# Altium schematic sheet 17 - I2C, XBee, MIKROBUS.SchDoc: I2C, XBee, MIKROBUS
size A3; PageSetup: Record=PageOptions¦CenterHorizontal=True¦CenterVertical=True¦PrintScale=0.70¦XCorrection=1.00¦YCorrection=1.00¦PrintKind=0¦BorderSize=5000000¦LeftOffset=0¦BottomOffset=0¦Orientation=2¦PaperLength=4200¦PaperWidth=2970¦Scale=100¦PaperSource=7¦PrintQuality=600¦MediaType=1¦DitherType=10¦PaperKind=A4¦PrintScaleMode=1; Author: Juan Anzola; SheetNumber: 17; SheetTotal: 20
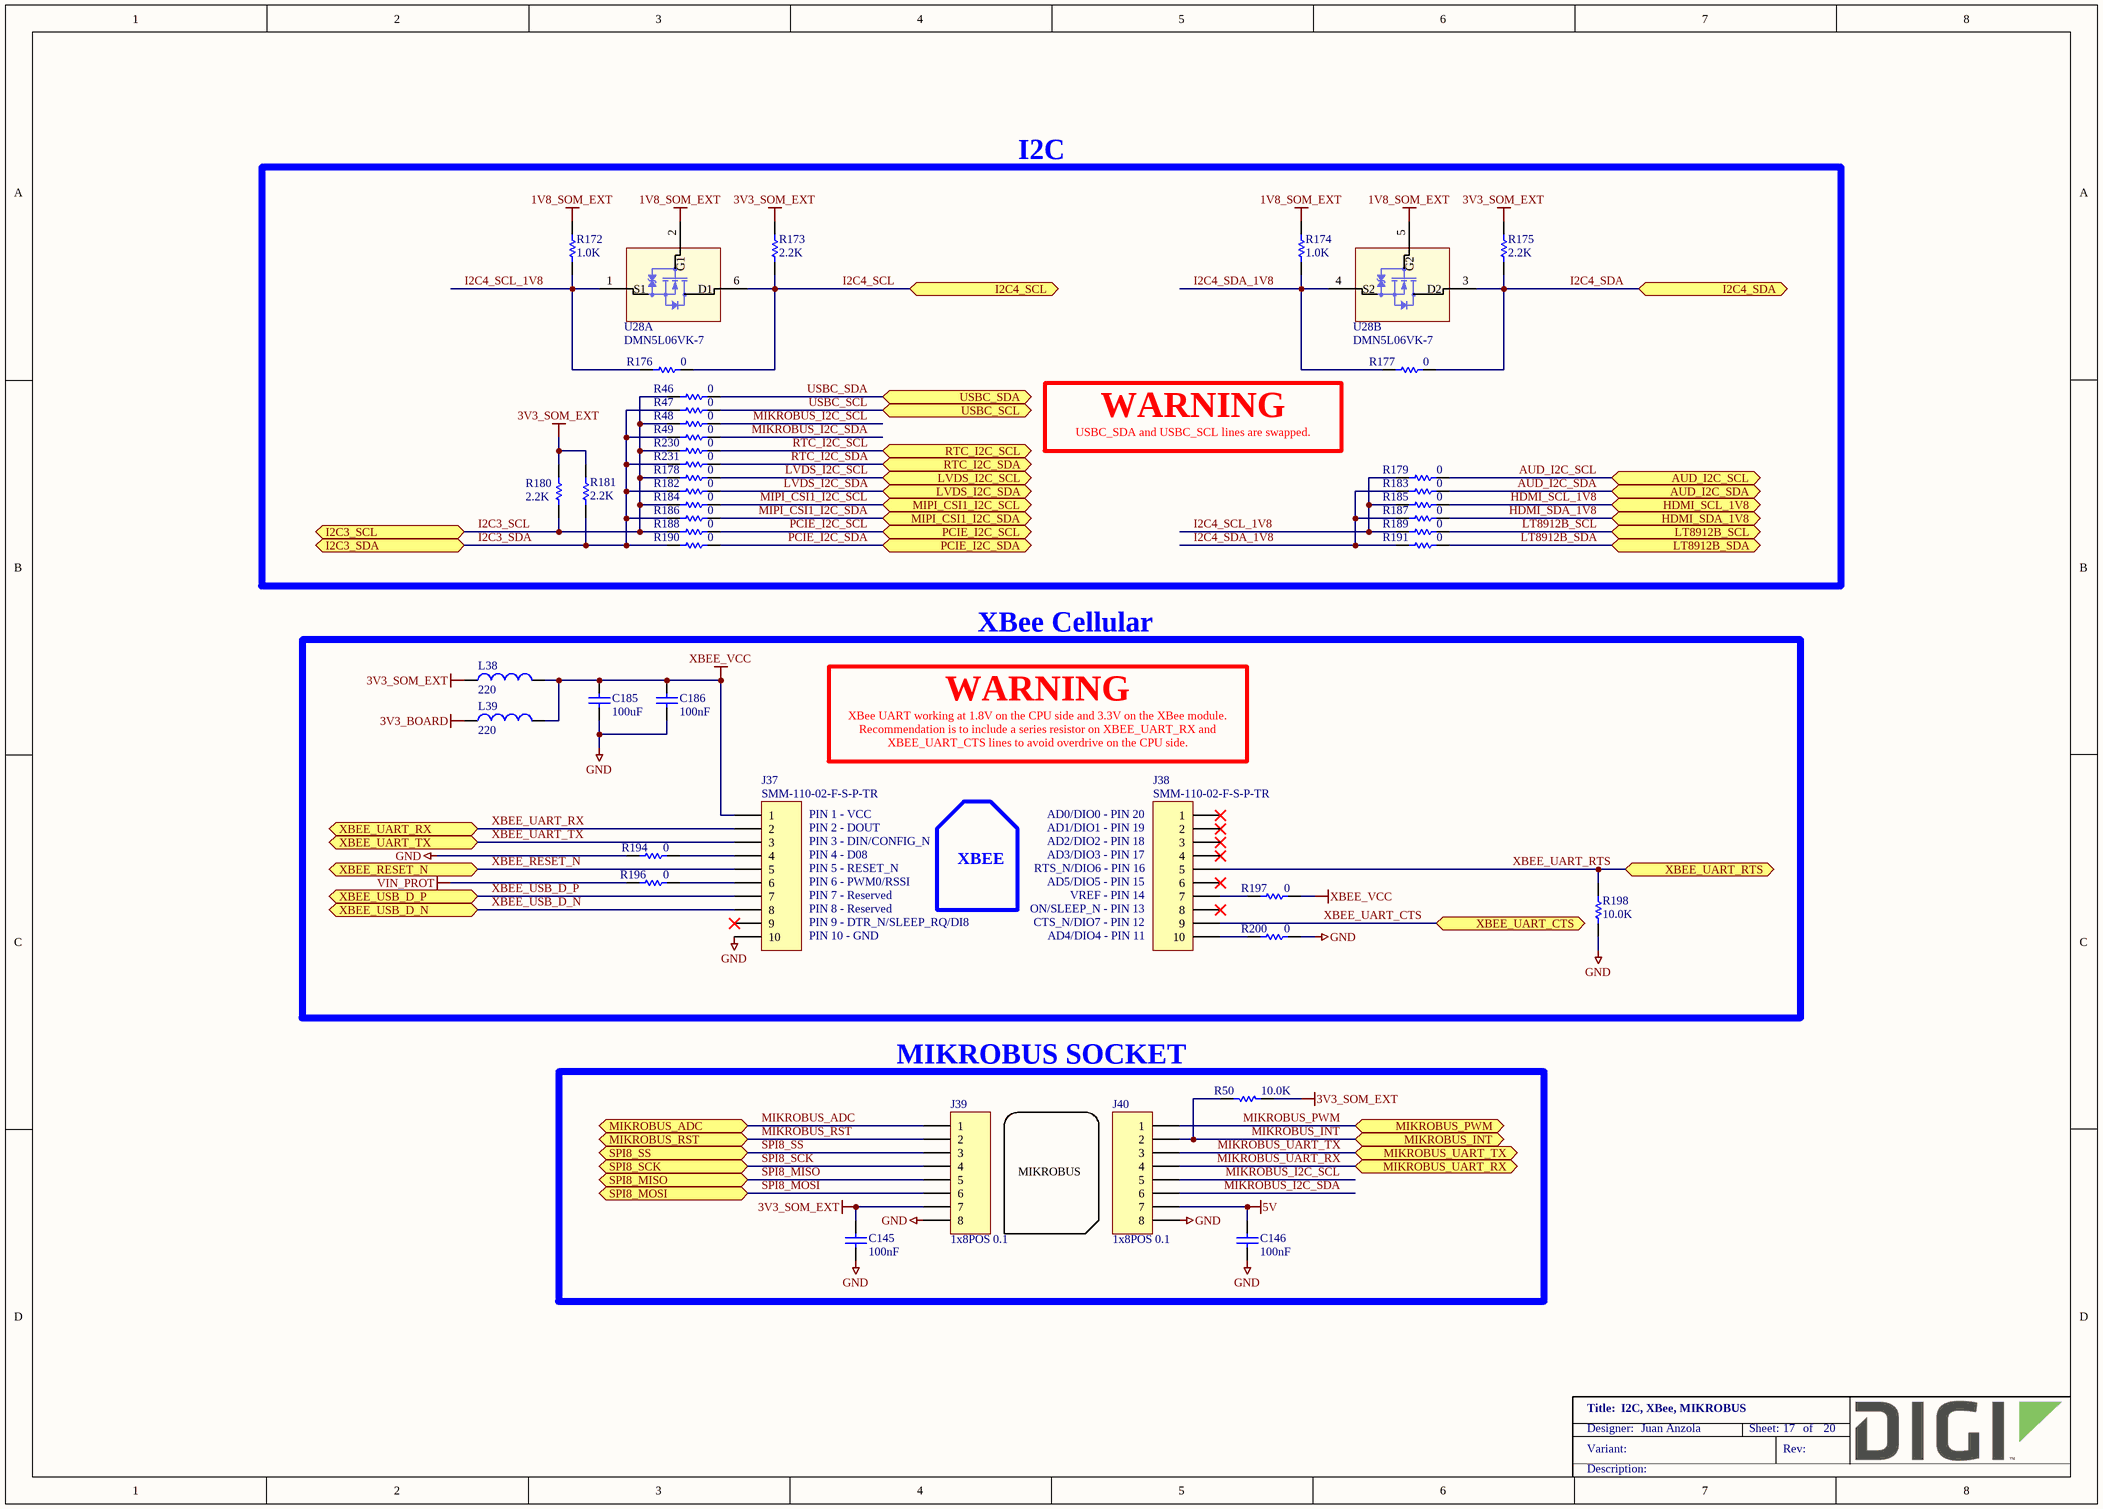
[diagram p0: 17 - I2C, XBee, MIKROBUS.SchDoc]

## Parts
C145  100nF  [CAPC1005X55N]
C146  100nF  [CAPC1005X55N]
C185  100uF  [CAPC3216X190N]
C186  100nF  [CAPC1005X55N]
J37  SMM-110-02-F-S-P-TR  [Samtec_SMM-110-02-F-S]
J38  SMM-110-02-F-S-P-TR  [Samtec_SMM-110-02-F-S]
J39  1x8POS 0.1  [J8_THT_0.1_FEMALE]
J40  1x8POS 0.1  [J8_THT_0.1_FEMALE]
L38  220  [INDC2013X110N]
L39  220  [INDC2013X110N]
R46  0  [RESC1005X40N]
R47  0  [RESC1005X40N]
R48  0  [RESC1005X40N]
R49  0  [RESC1005X40N]
R50  10.0K  [RESC1005X40N]
R172  1.0K  [RESC1005X40N]
R173  2.2K  [RESC1005X40N]
R174  1.0K  [RESC1005X40N]
R175  2.2K  [RESC1005X40N]
R176  0  [RESC1005X40N]
R177  0  [RESC1005X40N]
R178  0  [RESC1005X40N]
R179  0  [RESC1005X40N]
R180  2.2K  [RESC1005X40N]
R181  2.2K  [RESC1005X40N]
R182  0  [RESC1005X40N]
R183  0  [RESC1005X40N]
R184  0  [RESC1005X40N]
R185  0  [RESC1005X40N]
R186  0  [RESC1005X40N]
R187  0  [RESC1005X40N]
R188  0  [RESC1005X40N]
R189  0  [RESC1005X40N]
R190  0  [RESC1005X40N]
R191  0  [RESC1005X40N]
R194  0  [RESC1005X40N]
R196  0  [RESC1005X40N]
R197  0  [RESC1005X40N]
R198  10.0K  [RESC1005X40N]
R200  0  [RESC1005X40N]
R230  0  [RESC1005X40N]
R231  0  [RESC1005X40N]
U28  DMN5L06VK-7  [SOTFL50P160X60-6N]  (parts A,B of 2)

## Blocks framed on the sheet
I2C: R46-R49 R172-R191 R230 R231 U28
XBee Cellular: C185 C186 J37 J38 L38 L39 R194 R196-R198 R200
MIKROBUS SOCKET: C145 C146 J39 J40 R50

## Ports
AUD_I2C_SCL (bidir), AUD_I2C_SDA (bidir), HDMI_SCL_1V8 (bidir), HDMI_SDA_1V8 (bidir), I2C3_SCL (bidir), I2C3_SDA (bidir), I2C4_SCL (bidir), I2C4_SDA (bidir), LT8912B_SCL (bidir), LT8912B_SDA (bidir), LVDS_I2C_SCL (bidir), LVDS_I2C_SDA (bidir), MIKROBUS_ADC (bidir), MIKROBUS_INT (bidir), MIKROBUS_PWM (bidir), MIKROBUS_RST (bidir), MIKROBUS_UART_RX (bidir), MIKROBUS_UART_TX (bidir), MIPI_CSI1_I2C_SCL (bidir), MIPI_CSI1_I2C_SDA (bidir), PCIE_I2C_SCL (bidir), PCIE_I2C_SDA (bidir), RTC_I2C_SCL (bidir), RTC_I2C_SDA (bidir), SPI8_MISO (bidir), SPI8_MOSI (bidir), SPI8_SCK (bidir), SPI8_SS (bidir), USBC_SCL (bidir), USBC_SDA (bidir), XBEE_RESET_N (bidir), XBEE_UART_CTS (bidir), XBEE_UART_RTS (bidir), XBEE_UART_RX (bidir), XBEE_UART_TX (bidir), XBEE_USB_D_N (bidir), XBEE_USB_D_P (bidir)

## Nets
1V8_SOM_EXT: R172.2 R174.2 U28.2(G1) U28.5(G2)
3V3_BOARD: L39.1
3V3_SOM_EXT: C145.2 J39.7 L38.1 R50.2 R173.2 R175.2 R180.2 R181.2
5V: C146.1 J40.7
GND: C145.1 C146.2 C185.1 C186.1 J37.10 J39.8 J40.8 R194.1 R198.1 R200.2
VIN_PROT: R196.1
XBEE_VCC: C185.2 C186.2 J37.1 L38.2 L39.2 R197.2
AUD_I2C_SCL: R179.2 ; port AUD_I2C_SCL
AUD_I2C_SDA: R183.2 ; port AUD_I2C_SDA
HDMI_SCL_1V8: R185.2 ; port HDMI_SCL_1V8
HDMI_SDA_1V8: R187.2 ; port HDMI_SDA_1V8
I2C3_SCL: R46.1 R48.1 R178.1 R180.1 R184.1 R188.1 R230.1 ; port I2C3_SCL
I2C3_SDA: R47.1 R49.1 R181.1 R182.1 R186.1 R190.1 R231.1 ; port I2C3_SDA
I2C4_SCL: R173.1 R176.2 U28.6(D1) ; port I2C4_SCL
I2C4_SCL_1V8: R172.1 R176.1 R179.1 R185.1 R189.1 U28.1(S1)
I2C4_SDA: R175.1 R177.2 U28.3(D2) ; port I2C4_SDA
I2C4_SDA_1V8: R174.1 R177.1 R183.1 R187.1 R191.1 U28.4(S2)
LT8912B_SCL: R189.2 ; port LT8912B_SCL
LT8912B_SDA: R191.2 ; port LT8912B_SDA
LVDS_I2C_SCL: R178.2 ; port LVDS_I2C_SCL
LVDS_I2C_SDA: R182.2 ; port LVDS_I2C_SDA
MIKROBUS_ADC: J39.1 ; port MIKROBUS_ADC
MIKROBUS_I2C_SCL: J40.5 R48.2
MIKROBUS_I2C_SDA: J40.6 R49.2
MIKROBUS_INT: J40.2 R50.1 ; port MIKROBUS_INT
MIKROBUS_PWM: J40.1 ; port MIKROBUS_PWM
MIKROBUS_RST: J39.2 ; port MIKROBUS_RST
MIKROBUS_UART_RX: J40.4 ; port MIKROBUS_UART_RX
MIKROBUS_UART_TX: J40.3 ; port MIKROBUS_UART_TX
MIPI_CSI1_I2C_SCL: R184.2 ; port MIPI_CSI1_I2C_SCL
MIPI_CSI1_I2C_SDA: R186.2 ; port MIPI_CSI1_I2C_SDA
PCIE_I2C_SCL: R188.2 ; port PCIE_I2C_SCL
PCIE_I2C_SDA: R190.2 ; port PCIE_I2C_SDA
RTC_I2C_SCL: R230.2 ; port RTC_I2C_SCL
RTC_I2C_SDA: R231.2 ; port RTC_I2C_SDA
SPI8_MISO: J39.5 ; port SPI8_MISO
SPI8_MOSI: J39.6 ; port SPI8_MOSI
SPI8_SCK: J39.4 ; port SPI8_SCK
SPI8_SS: J39.3 ; port SPI8_SS
USBC_SCL: R47.2 ; port USBC_SCL
USBC_SDA: R46.2 ; port USBC_SDA
XBEE_RESET_N: J37.5 ; port XBEE_RESET_N
XBEE_UART_CTS: J38.9 ; port XBEE_UART_CTS
XBEE_UART_RTS: J38.5 R198.2 ; port XBEE_UART_RTS
XBEE_UART_RX: J37.2 ; port XBEE_UART_RX
XBEE_UART_TX: J37.3 ; port XBEE_UART_TX
XBEE_USB_D_N: J37.8 ; port XBEE_USB_D_N
XBEE_USB_D_P: J37.7 ; port XBEE_USB_D_P
NetJ37_4: J37.4 R194.2
NetJ37_6: J37.6 R196.2
NetJ38_7: J38.7 R197.1
NetJ38_10: J38.10 R200.1

Not connected (* = marked no-connect by the designer): J37 9*; J38 1* 2* 3* 4* 6* 8*

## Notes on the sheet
- WARNING
- USBC_SDA and USBC_SCL lines are swapped.
- XBee UART working at 1.8V on the CPU side and 3.3V on the XBee module. Recommendation is to include a series resistor on XBEE_UART_RX and XBEE_UART_CTS lines to avoid overdrive on the CPU side.
- (near J37) PIN 1 - VCC
- (near J37) PIN 2 - DOUT
- (near J37) PIN 3 - DIN/CONFIG_N
- (near J37) PIN 4 - D08
- (near J38) AD0/DIO0 - PIN 20
- (near J38) AD1/DIO1 - PIN 19
- (near J38) AD2/DIO2 - PIN 18
- (near J38) AD3/DIO3 - PIN 17
- (near J37) PIN 5 - RESET_N
- (near J37) PIN 6 - PWM0/RSSI
- (near J37) PIN 7 - Reserved
- (near J37) PIN 8 - Reserved
- XBEE
- (near J38) RTS_N/DIO6 - PIN 16
- (near J38) AD5/DIO5 - PIN 15
- (near J38) VREF - PIN 14
- (near J38) ON/SLEEP_N - PIN 13
- (near J37) PIN 9 - DTR_N/SLEEP_RQ/DI8
- (near J37) PIN 10 - GND
- (near J38) CTS_N/DIO7 - PIN 12
- (near J38) AD4/DIO4 - PIN 11
- MIKROBUS

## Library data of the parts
C145 = 1000006: CAP 100nF 16V 10% X7R 0402; Part_Type: Capacitor; Manufacturer: Murata; Manufacturer_Part_Number: GRM155R71C104KA88D; Digi_PN: 14050552; Component_Life_Cycle_State: CAD Reviewed; Area: 0,95; Tolerance: 10
C146 C186 = 1000006: CAP 100nF 16V 10% X7R 0402; Part_Type: Capacitor; Manufacturer: Murata; Manufacturer_Part_Number: GRM155R71C104KA88D; Component_Life_Cycle_State: CAD Reviewed; Area: 0.95; Project: KITT; Tolerance: 10; Digi_PN: 14050552
C185 = 1000566: CAP CER 100UF 10V 20% X5R 1206; Part_Type: Capacitor; Manufacturer: TDK Corporation; Manufacturer_Part_Number: C3216X5R1A107M; Digi_PN: 14050666; Component_Life_Cycle_State: Reviewed; Area: 7.47; Project: GSM Cell PCB
J37 J38 = 1001495: CONN RCPT 2MM 10POS SMD; Part_Type: Connector; Manufacturer: Samtec; Digi_PN: 19050036; Component_Life_Cycle_State: Reviewed; Area: 105; Project: CCWMX6_SBC board
J39 J40 = 1002848: CONN HDR 8POS 0.1 GOLD PCB; Part_Type: Connector; Manufacturer: Sullins; Manufacturer_Part_Number: PPPC081LFBN-RC; Digi_PN: 18000876; Component_Life_Cycle_State: Pending
L38 L39 = 1001174: FERRITE BEAD 220 OHM 2.0A 0805; Manufacturer: Wurth Electronics Inc; Manufacturer_Part_Number: 742792022; Digi_PN: 21000146; Component_Life_Cycle_State: Reviewed; Area: 4.24; Project: CCWMX6_SBC board
R46-R49 R176 R177 R230 R231 = 1000076: RES 0.0 OHM 1/10W 0402 SMD; Part_Type: Resistor; Manufacturer: Panasonic - ECG; Manufacturer_Part_Number: ERJ-2GE0R00X; Digi_PN: 13050387; Component_Life_Cycle_State: Proven; Area: 0,95; Power_WV_SRF: 10
R50 R198 = 1000537: RES 10.0K OHM 1/10W 1% 0402 SMD; Part_Type: Resistor; Manufacturer: Panasonic - ECG; Manufacturer_Part_Number: ERJ-2RKF1002X; Component_Life_Cycle_State: CAD Reviewed; Area: 0.95; Project: KITT; Power_WV_SRF: 100; Digi_PN: 13051084
R172 R174 = 1000079: RES 1.00K OHM 1/10W 1% 0402 SMD; Part_Type: Resistor; Manufacturer: Panasonic - ECG; Manufacturer_Part_Number: ERJ-2RKF1001X; Digi_PN: 13051085; Component_Life_Cycle_State: Proven; Area: 0,95; Project: Adjustable Foundation; Power_WV_SRF: 10
R173 R175 = 1001156: RES 2.20K OHM 1/16W 1% 0402 SMD; Part_Type: Resistor; Manufacturer: Yageo; Manufacturer_Part_Number: RC0402FR-072K2L; Note: 13051099 = Digi No. for GE WDNU; Digi_PN: 13050699; Component_Life_Cycle_State: Reviewed; Area: 0,95
R178 R179 R182-R191 R194 R196 R197 R200 = 1000076: RES 0.0 OHM 1/10W 0402 SMD; Part_Type: Resistor; Manufacturer: Panasonic - ECG; Manufacturer_Part_Number: ERJ-2GE0R00X; Component_Life_Cycle_State: Proven; Area: 0.95; Project: Adjustable Foundation; Power_WV_SRF: 10; Digi_PN: 13050387
R180 R181 = 1001156: RES 2.20K OHM 1/16W 1% 0402 SMD; Part_Type: Resistor; Manufacturer: Yageo; Manufacturer_Part_Number: RC0402FR-072K2L; Digi_PN: 13050699; Component_Life_Cycle_State: Reviewed; Area: 0.95; Project: CCWMX6_SBC board; Note: 13051099 = Digi No. for GE WDNU
U28 = 1002493: MOSFET 2N-CH 30V 0.1A ES6; Part_Type: Transistor; Manufacturer: Diodes, Inc.; Digi_PN: 17000134; Component_Life_Cycle_State: Reviewed; Area: 4,88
